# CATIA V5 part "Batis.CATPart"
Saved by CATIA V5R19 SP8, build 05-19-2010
Part number: Batis
Bounding box of the stored display mesh (mm): x -37 to 4, y -48 to 48, z -39 to 35
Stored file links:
  C:\Users\ThinkMotion\Desktop\EU_thinkMotion\iao\IAO_MMS_Groupe3\ecartoux\projet_IAO_ecartoux\projet_IAO_ecartoux\griffe_d'une_camera_ecartoux\Batis.CATPart
  C:\Users\ThinkMotion\Desktop\EU_thinkMotion\iao\IAO_MMS_Groupe3\ecartoux\projet_IAO_ecartoux\projet_IAO_ecartoux\griffe_d'une_camera_ecartoux\Mecanisme_a_coulisse_et_leviers_de_la_griffe_d'un_camera_ecartoux.CATProduct
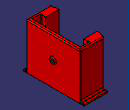
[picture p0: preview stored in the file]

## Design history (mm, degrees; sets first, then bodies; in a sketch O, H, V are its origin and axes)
Set1
  Plane1: linked copy from another document
  Point1 to Point3: linked copy from another document
  Plane2: linked copy from another document
Body1 (main body)
  Sketch1 on Plane1, origin (0, 0, 0), H (1, 0, 0), V (0, 1, 0)
    point P1 (-16, 35.5)
    line L1 (-37, 35.5) -> (-37, 30)
    line L2 (-37, 30) -> (-16, 30)
    line L3 (-16, 30) -> (-16, 35.5)
    point P2 (-37, 35.5)
    point P3 (-37, 30)
    point P4 (-16, 30)
    reference projected point E1 (-16, 30) from Point1
    reference projected point E2 (-37, 30) from Point2
    axis line L4 (17.4857, 0) -> (-71.5587, 0)
    point P5 (17.4857, 0)
    point P7 (2.5, 0)
    line L5 (-2.5, 0) -> (-2.5, 38.5833)
    line L6 (2.5, 43) -> (2.5, 0)
    point P8 (-2.5, 0)
    point P9 (2.5, 43)
    point P10 (2.5, 43)
    reference projected point E3 (0, 0) from Point3
    line L7 (2.5, 43) -> (-35.5, 43)
    line L8 (-35.5, 43) -> (-35.5, 38.5)
    point P11 (-35.5, 43)
    point P12 (-35.5, 38.5)
    point P13 (-2.5, 38.5833)
    line L9 (-2.5, 38.5833) -> (-16, 38.5833)
    point P14 (-2.5, 38.5833)
    point P15 (-16, 38.5833)
    arc A1 centre (-39.25, 38.5) radius 3.75 from (-37, 35.5) to (-35.5, 38.5) ccw
    arc A2 centre (-16, 37.0417) radius 1.5417 from (-16, 35.5) to (-16, 38.5833) cw
    point P18 (0, 0)
    point P19 (0, 0)
    point P20 (-37, -30)
    point P21 (-37, -35.5)
    line L10 (-37, -35.5) -> (-37, -30)
    point P22 (-35.5, -38.5)
    arc A3 centre (-39.25, -38.5) radius 3.75 from (-37, -35.5) to (-35.5, -38.5) cw
    point P24 (-35.5, -43)
    line L11 (-35.5, -43) -> (-35.5, -38.5)
    point P25 (2.5, -43)
    line L12 (2.5, -43) -> (-35.5, -43)
    point P26 (-16, -30)
    line L13 (-37, -30) -> (-16, -30)
    point P27 (-16, -35.5)
    line L14 (-16, -30) -> (-16, -35.5)
    point P28 (-16, -38.5833)
    arc A4 centre (-16, -37.0417) radius 1.5417 from (-16, -35.5) to (-16, -38.5833) ccw
    point P30 (-2.5, -38.5833)
    line L15 (-2.5, -38.5833) -> (-16, -38.5833)
    point P31 (-2.5, -38.5833)
    point P32 (-2.5, 0)
    line L16 (-2.5, 0) -> (-2.5, -38.5833)
    point P33 (2.5, 0)
    point P34 (2.5, -43)
    line L17 (2.5, -43) -> (2.5, 0)
    distance L6 L5 = 5
    distance L6 E3 = 2.5
    distance L5 L8 = 33
    distance L9 L7 = 4.4167
    radius A1 = 3.75
    radius A2 = 1.5417
    length L1 = 5.5
    length L3 = 5.5
    length L9 = 13.5
    horizontal: L2 H, L4 H, L7 H, L9 H
    vertical: L1 V, L3 V, L5 V, L6 V, L8 V
    coincidence: P4 E1, P3 E2, P5 H, L4 P7, L4 P8, P14 L5, P9 P10, P13 P14, P7 P33, P8 P32, P25 P34, P30 P31
    tangency: A1 L8, A2 L9
    perpendicularity: L3 L9
    symmetry: P3 P20 L4, P2 P21 L4, L1 L10 L4, P12 P22 L4, A1 A3 L4, P11 P24 L4, L8 L11 L4, P9 P25 L4, L7 L12 L4, P4 P26 L4, L2 L13 L4, P1 P27 L4, L3 L14 L4, P15 P28 L4, A2 A4 L4, P14 P30 L4, L9 L15 L4, P13 P31 L4, P8 P32 L4, L5 L16 L4, P7 P33 L4, P10 P34 L4, L6 L17 L4
  Pad1: profile Sketch1, direction (0, 0, 1), length 35, mirrored extent
  Sketch2 on Plane1, origin (0, 0, 0), H (1, 0, 0), V (0, 1, 0)
    line L1 (-35.5, 48) -> (2.5, 48)
    line L2 (2.5, 48) -> (2.5, -48)
    line L3 (2.5, -48) -> (-35.5, -48)
    line L4 (-35.5, -48) -> (-35.5, 48)
    reference projected point E1 (0, 0) from Point3
    reference projected point E2 (0, 0) from Point3
    distance L2 L4 = 38
    distance E1 L2 = 2.5
    distance L3 L1 = 96
    distance E2 L1 = 48
    horizontal: L1 H, L3 H
    vertical: L2 V, L4 V
  Pad2: profile Sketch2, direction (0, 0, -1), length 39, opposite side length -35
  Sketch3 on Plane2, origin (0, 0, 0), H (0, 1, 0), V (0, 0, 1)
    circle A1 centre (0, 0) radius 4
    point P1 (0, 0)
    reference projected point E1 (0, 0) from Point3
    radius A1 = 4
    coincidence: P1 E1
  Pad3: profile Sketch3, direction (1, 0, 0), length 4, opposite side length 5
  Sketch4 on Plane2, origin (0, 0, 0), H (0, 1, 0), V (0, 0, 1)
    circle A1 centre (0, 0) radius 2
    point P1 (0, 0)
    reference projected point E1 (0, 0) from Point3
    radius A1 = 2
    coincidence: P1 E1
  Pocket1: profile Sketch4, direction (-1, 0, 0), length 5, mirrored extent
  Fillet1: radius 2.5, on edge [face of Pad3 from Sketch3.A1 | face of Pad1 from Sketch1.L5]; edge [face of Pad3 from Sketch3.A1 | face of Pad1 from Sketch1.L16]
  Fillet2: radius 1.5, on face of Pad2
  Fillet3: radius 2, on edge [face of Pad2 from Sketch2.L1 | start face of Pad2]; edge [face of Pad2 from Sketch2.L3 | start face of Pad2]; edge [start face of Pad2 | face of Pad1 from Sketch1.L12]; edge [start face of Pad2 | face of Pad1 from Sketch1.L7]; edge [face of Pad1 from Sketch1.L7 | end face of Pad1]; edge [face of Pad1 from Sketch1.L12 | end face of Pad1]; edge [face of Pad2 | face of Pad1 from Sketch1.L7]; edge [face of Pad1 from Sketch1.L12 | face of Pad2]; edge [face of Pad2 | start face of Pad2] (x3)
